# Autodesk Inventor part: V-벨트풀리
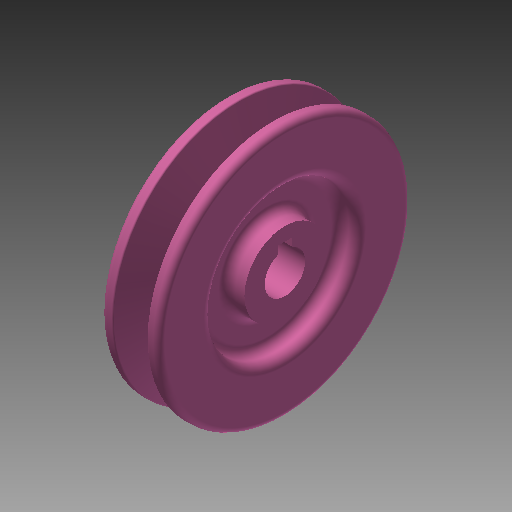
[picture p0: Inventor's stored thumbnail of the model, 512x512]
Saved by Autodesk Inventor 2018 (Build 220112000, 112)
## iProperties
Created: 2019-09
Part Number: V-벨트풀리
Material: 알루미늄 6061
Document SubType Name: Modeling
Designer: mduedu
Density: 1 g/cm^3
Appearance: 분홍색
Author: mduedu
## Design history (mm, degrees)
sketch "스케치1"
  geometry: L1 (-10, 0)-(10, 0); L2 (10, 0)-(10, 43.5); L3 (10, 43.5)-(-10, 43.5); L4 (-10, 43.5)-(-10, 0); L5 (0, 0)-(0, 43.5); L6 (-5.976, 43.5)-(-2.154, 31); L7 (-2.154, 31)-(2.154, 31); L8 (2.154, 31)-(5.976, 43.5); L9 (-10, 39)-(10, 39); 3 further points
  constraints: 18 end point, 8 point on line, 3 perpendicular, 2 midpoint, 2 parallel, 1 coincident, 1 horizontal, 1 other
  dimensions: "d0" = 87 diameter of L3 L1; "d3" = 12.5 distance between parallel lines of L7 L3; "d4" = 34 deg angle of L8 L6; "d5" = 20 distance between parallel lines of L2 L4; "d6" = 8 distance between parallel lines of L9 L7; "d7" = 9.2 distance of point (4.6, 39) point (-4.6, 39)
revolve "회전1" sketch "스케치1" stored, may be unused: angle "d8" = 90 deg
sketch "스케치2"
  geometry: C1 r 14 at (0, 0); C2 r 25 at (0, 0); 1 further point
  constraints: 2 centre point, 2 coincident
  dimensions: "d9" = 28 diameter of C1; "d10" = 50 diameter of C2
extrude "돌출1" cut sketch "스케치2" distance "d11" = 6; taper "d12" = 0 deg
fillet "모깎기1" dims "d13" = 3
fillet "모깎기2" dims "d14" = 3
fillet "모깎기3" dims "d15" = 0.5, "d16" = 1, "d17" = 2
sketch "스케치3"
  geometry: L1 (-2.5, 6.538)-(2.5, 6.538); L2 (2.5, 6.538)-(2.5, 9.3); L3 (2.5, 9.3)-(-2.5, 9.3); L4 (-2.5, 9.3)-(-2.5, 6.538); A1 r 7 centre (0, 0) between (-2.5, 6.538) and (2.5, 6.538); 1 further point
  constraints: 8 end point, 2 parallel, 2 point on circle, 1 centre point, 1 coincident, 1 horizontal, 1 perpendicular
  dimensions: "d18" = 14 diameter of A1; "d20" = 5 distance of L2.end L3.end; "d21" = 16.3 dimension on A1 L3
extrude "돌출2" cut sketch "스케치3" extent not by distance; stored distance "d22" = 6; taper "d23" = 0 deg
node "솔리드1"
mirror "대칭1"
